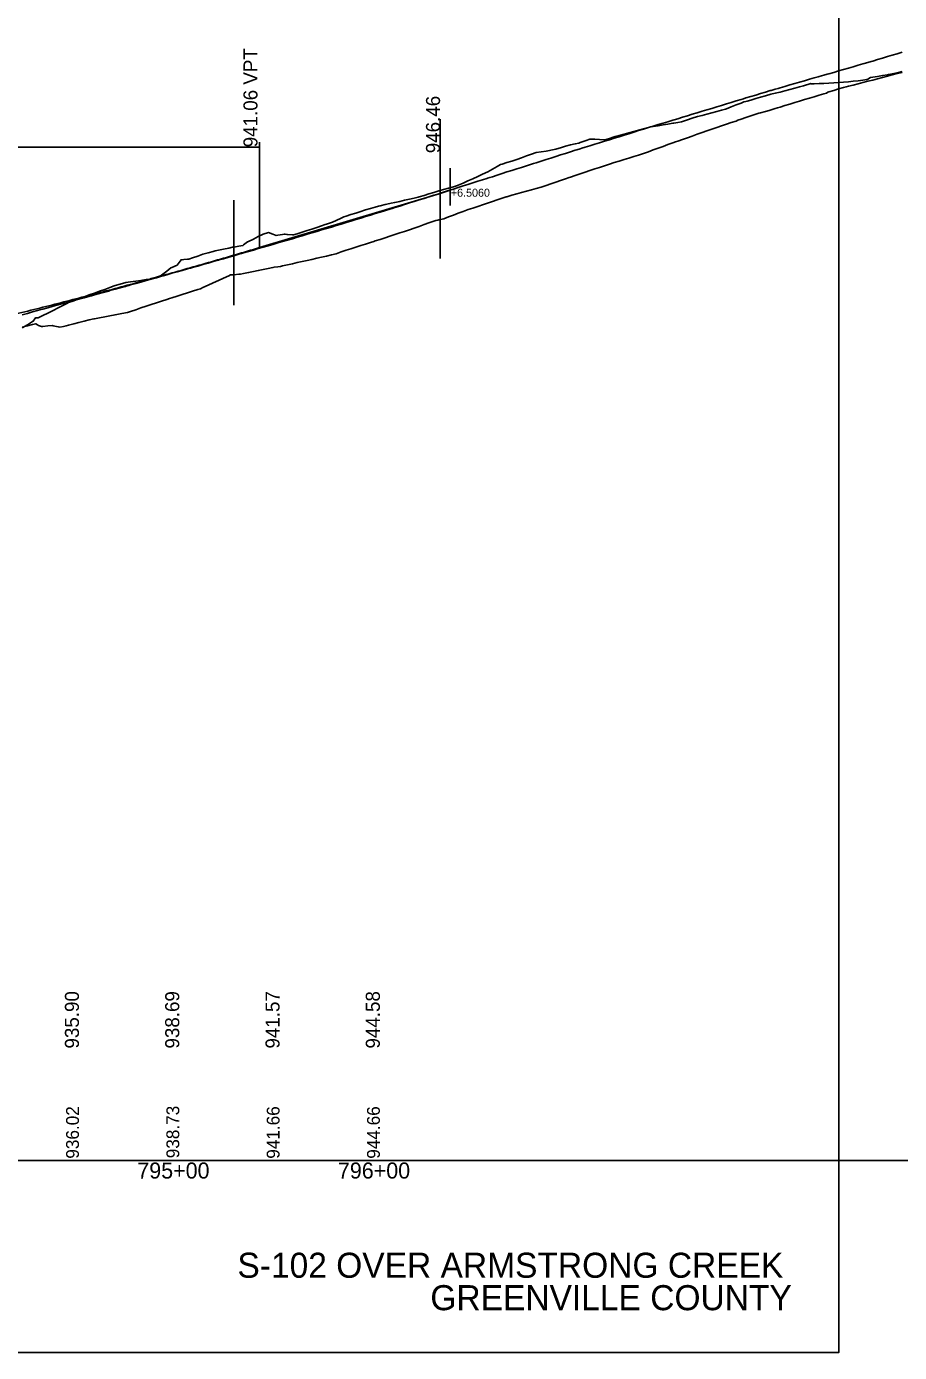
# Model space of a CAD drawing. Extents: x 1558113 to 1562835, y 1129435 to 1135883.
# Drawn here: x 1560920 to 1561355, y 1133348 to 1134009 of the extents above; entities that cross this region are included whole.
import ezdxf

# ---------------------------------------------------------------- set-up
doc = ezdxf.new("R2010")
doc.units = 0
for name, color, linetype in [('BR_EXIST_GROUND_LT', 7, 'Continuous'), ('BR_EXIST_GROUND_RT', 7, 'Continuous'), ('BR_USER NOTES', 7, 'Continuous'), ('RD_DDB_Profile_EX', 7, 'Continuous'), ('RD_DDB_Profile_Lbl', 7, 'Continuous'), ('RD_DDB_Profile_PR', 7, 'Continuous'), ('RD_DDB_StaTX', 7, 'Continuous'), ('RD_DDB_StripGrade', 7, 'Continuous'), ('RD_DDB_VCLbl', 7, 'Continuous'), ('RD_GPK_Profile_Cell', 7, 'Continuous'), ('RD_SHT_ShtClip', 7, 'Continuous'), ('RD_SHT_TX', 7, 'Continuous')]:
    doc.layers.add(name, color=color, linetype=linetype)

msp = doc.modelspace()

# ---------------------------------------------------------------- linework, layer by layer
at = {"layer": 'BR_EXIST_GROUND_LT'}
msp.add_lwpolyline([(1560918.07, 1133859.11), (1560920.65, 1133860.63), (1560923.22, 1133862.17), (1560923.59, 1133862.4), (1560924.66, 1133864.04), (1560925.98, 1133864.05), (1560928.37, 1133865.21), (1560930.94, 1133866.48), (1560933.52, 1133867.78), (1560936.09, 1133869.09), (1560938.66, 1133870.43), (1560940.26, 1133871.27), (1560941.24, 1133871.64), (1560943.81, 1133872.61), (1560946.39, 1133873.6), (1560947.43, 1133874), (1560948.96, 1133874.55), (1560950.25, 1133875.02), (1560951.53, 1133875.47), (1560954.11, 1133876.4), (1560956.68, 1133877.33), (1560959.26, 1133878.26), (1560961.83, 1133879.21), (1560963.97, 1133880), (1560964.4, 1133880.12), (1560966.98, 1133880.85), (1560969.81, 1133881.66), (1560972.13, 1133881.99), (1560974.7, 1133882.36), (1560977.27, 1133882.74), (1560979.85, 1133883.12), (1560981.76, 1133883.41), (1560982.42, 1133883.61), (1560985, 1133884.4), (1560987.09, 1133885.05), (1560987.57, 1133885.42), (1560990.14, 1133887.4), (1560992.17, 1133888.96), (1560992.72, 1133889.19), (1560995.29, 1133890.27), (1560997.29, 1133893.02), (1560997.87, 1133893.07), (1560998.72, 1133893.13), (1561000.44, 1133893.26), (1561001.12, 1133893.31), (1561003.02, 1133893.98), (1561005.59, 1133894.9), (1561008.2, 1133895.82), (1561009.4, 1133896.1), (1561010.74, 1133896.47), (1561013.31, 1133897.19), (1561014.24, 1133897.45), (1561015.89, 1133897.8), (1561018.46, 1133898.34), (1561021.03, 1133898.88), (1561022.88, 1133899.27), (1561023.61, 1133899.39), (1561026.04, 1133899.78), (1561028.1, 1133900.12), (1561028.47, 1133900.41), (1561030.38, 1133901.95), (1561030.9, 1133902.2), (1561033.33, 1133903.38), (1561035.76, 1133904.57), (1561038.23, 1133905.77), (1561040.82, 1133906.57), (1561043.06, 1133905.71), (1561044.68, 1133905.09), (1561045.49, 1133905.22), (1561047.92, 1133905.61), (1561048.66, 1133905.73), (1561049.18, 1133905.71), (1561049.98, 1133905.59), (1561050.35, 1133905.57), (1561052.78, 1133905.44), (1561053.27, 1133905.42), (1561055.21, 1133906.03), (1561057.64, 1133906.8), (1561060.07, 1133907.58), (1561062.5, 1133908.36), (1561064.93, 1133909.15), (1561067.36, 1133909.95), (1561069.13, 1133910.54), (1561069.8, 1133910.75), (1561072.23, 1133911.53), (1561072.81, 1133911.72), (1561074.66, 1133912.61), (1561077.09, 1133913.79), (1561078.44, 1133914.45), (1561079.52, 1133914.79), (1561081.95, 1133915.55), (1561084.38, 1133916.31), (1561086.81, 1133917.08), (1561088.74, 1133917.7), (1561089.24, 1133917.85), (1561091.67, 1133918.58), (1561094.11, 1133919.32), (1561095.69, 1133919.8), (1561096.54, 1133919.99), (1561098.97, 1133920.53), (1561101.4, 1133921.08), (1561102.03, 1133921.22), (1561103.83, 1133921.62), (1561106.26, 1133922.15), (1561108.69, 1133922.69), (1561111.12, 1133923.24), (1561113.55, 1133923.79), (1561115.41, 1133924.22), (1561115.98, 1133924.39), (1561118.42, 1133925.13), (1561120.85, 1133925.87), (1561123.28, 1133926.62), (1561125.74, 1133927.39), (1561128.14, 1133928.06), (1561130.57, 1133928.75), (1561133, 1133929.44), (1561135.05, 1133930.03), (1561135.43, 1133930.2), (1561137.86, 1133931.29), (1561140.29, 1133932.37), (1561142.73, 1133933.46), (1561145.16, 1133934.55), (1561147.59, 1133935.65), (1561150.25, 1133936.86), (1561152.45, 1133938.14), (1561154.88, 1133939.56), (1561156.52, 1133940.52), (1561157.31, 1133940.76), (1561159.74, 1133941.51), (1561162.17, 1133942.26), (1561162.58, 1133942.38), (1561164.6, 1133943.09), (1561167.03, 1133943.94), (1561169.47, 1133944.8), (1561171.9, 1133945.65), (1561174.28, 1133946.49), (1561176.76, 1133946.87), (1561179.19, 1133947.24), (1561180.9, 1133947.5), (1561181.62, 1133947.66), (1561184.05, 1133948.19), (1561184.59, 1133948.3), (1561186.48, 1133948.87), (1561188.91, 1133949.6), (1561191.46, 1133950.36), (1561193.78, 1133950.84), (1561195.56, 1133951.21), (1561196.21, 1133951.43), (1561198.64, 1133952.29), (1561199.7, 1133952.67), (1561200.52, 1133952.93), (1561201.07, 1133953.1), (1561201.44, 1133953.22), (1561203.5, 1133953.11), (1561205.93, 1133952.98), (1561208.48, 1133952.86), (1561210.79, 1133953.55), (1561213.22, 1133954.29), (1561213.75, 1133954.45), (1561215.65, 1133955), (1561218.09, 1133955.71), (1561218.74, 1133955.91), (1561220.54, 1133956.31), (1561222.95, 1133956.97), (1561225.38, 1133957.65), (1561227.81, 1133958.32), (1561230.25, 1133959.01), (1561231.24, 1133959.29), (1561232.67, 1133959.51), (1561235.1, 1133959.89), (1561237.53, 1133960.29), (1561239.96, 1133960.69), (1561242.4, 1133961.1), (1561242.83, 1133961.18), (1561244.83, 1133961.53), (1561246.79, 1133961.89), (1561247.26, 1133962.04), (1561249.69, 1133962.8), (1561252.12, 1133963.57), (1561254.76, 1133964.42), (1561256.98, 1133964.99), (1561259.41, 1133965.62), (1561261.84, 1133966.27), (1561264.27, 1133966.93), (1561266.7, 1133967.6), (1561268.6, 1133968.12), (1561269.14, 1133968.33), (1561271.57, 1133969.27), (1561274, 1133970.23), (1561276.43, 1133971.19), (1561277.8, 1133971.74), (1561278.86, 1133972.02), (1561279.43, 1133972.17), (1561281.29, 1133972.69), (1561283.72, 1133973.38), (1561286.15, 1133974.08), (1561288.58, 1133974.78), (1561291.21, 1133975.55), (1561293.45, 1133976.06), (1561295.88, 1133976.65), (1561298.31, 1133977.26), (1561300.74, 1133977.89), (1561303.17, 1133978.54), (1561305.6, 1133979.22), (1561307.52, 1133979.77), (1561308.03, 1133979.92), (1561310.68, 1133980.72), (1561311.06, 1133980.91), (1561311.43, 1133980.76), (1561312.89, 1133980.79), (1561315.32, 1133980.87), (1561317.76, 1133980.97), (1561320.19, 1133981.09), (1561322.62, 1133981.23), (1561325.05, 1133981.41), (1561327.48, 1133981.6), (1561329.91, 1133981.82), (1561332.34, 1133982.06), (1561334.77, 1133982.33), (1561337.2, 1133982.61), (1561339.15, 1133982.87), (1561339.63, 1133983.15), (1561340.94, 1133983.91), (1561342.06, 1133984.09), (1561344.5, 1133984.48), (1561346.93, 1133984.9), (1561349.36, 1133985.33), (1561349.91, 1133985.44), (1561351.79, 1133985.81), (1561354.22, 1133986.32), (1561356.65, 1133986.84)], dxfattribs=at)
at = {"layer": 'BR_EXIST_GROUND_RT'}
msp.add_lwpolyline([(1560918.07, 1133859.47), (1560920.65, 1133860.09), (1560923.22, 1133860.71), (1560924.86, 1133861.11), (1560925.79, 1133860.51), (1560926.14, 1133860.29), (1560927.65, 1133859.77), (1560928.37, 1133859.83), (1560930.94, 1133860.06), (1560933.09, 1133860.24), (1560933.52, 1133860.15), (1560936.09, 1133859.6), (1560936.79, 1133859.45), (1560938.66, 1133859.82), (1560939.93, 1133860.14), (1560941.24, 1133860.48), (1560943.81, 1133861.14), (1560946.39, 1133861.79), (1560948.96, 1133862.42), (1560951.53, 1133863.05), (1560953.75, 1133863.57), (1560954.11, 1133863.64), (1560956.68, 1133864.14), (1560959.26, 1133864.63), (1560961.83, 1133865.12), (1560964.4, 1133865.59), (1560966.98, 1133866.06), (1560969.55, 1133866.52), (1560970.59, 1133866.71), (1560972.13, 1133867.24), (1560974.7, 1133868.13), (1560977.27, 1133869.01), (1560979.85, 1133869.89), (1560982.42, 1133870.75), (1560985, 1133871.61), (1560987.57, 1133872.46), (1560990.14, 1133873.28), (1560991.59, 1133873.73), (1560992.72, 1133874.1), (1560995.29, 1133874.93), (1560997.87, 1133875.76), (1561000.44, 1133876.58), (1561003.02, 1133877.4), (1561005.59, 1133878.2), (1561006.9, 1133878.61), (1561008.16, 1133879.17), (1561010.74, 1133880.32), (1561013.31, 1133881.48), (1561015.89, 1133882.66), (1561018.46, 1133883.84), (1561021.03, 1133885.04), (1561021.9, 1133885.45), (1561023.61, 1133885.59), (1561026.04, 1133885.8), (1561026.87, 1133885.88), (1561028.47, 1133886.19), (1561030.9, 1133886.67), (1561033.33, 1133887.16), (1561035.76, 1133887.65), (1561038.19, 1133888.15), (1561040.62, 1133888.65), (1561043.06, 1133889.16), (1561043.75, 1133889.31), (1561045.49, 1133889.53), (1561046.8, 1133889.7), (1561047.92, 1133889.95), (1561050.35, 1133890.5), (1561052.78, 1133891.05), (1561055.21, 1133891.59), (1561057.64, 1133892.14), (1561060.07, 1133892.69), (1561062.5, 1133893.24), (1561064.93, 1133893.78), (1561067.36, 1133894.33), (1561069.8, 1133894.88), (1561072.23, 1133895.43), (1561074.66, 1133896.01), (1561077.09, 1133897.02), (1561079.52, 1133897.78), (1561081.95, 1133898.54), (1561084.38, 1133899.3), (1561086.81, 1133900.07), (1561089.24, 1133900.85), (1561091.67, 1133901.63), (1561093.44, 1133902.19), (1561094.11, 1133902.44), (1561096.54, 1133903.21), (1561098.97, 1133903.99), (1561101.4, 1133904.78), (1561103.83, 1133905.58), (1561106.26, 1133906.38), (1561108.69, 1133907.2), (1561111.12, 1133908.02), (1561113.55, 1133908.85), (1561115.98, 1133909.69), (1561118.42, 1133910.54), (1561120.85, 1133911.4), (1561123.28, 1133912.26), (1561124.2, 1133912.59), (1561125.26, 1133912.81), (1561125.71, 1133912.91), (1561128.3, 1133913.52), (1561130.57, 1133914.38), (1561133, 1133915.3), (1561135.43, 1133916.21), (1561137.86, 1133917.11), (1561140.45, 1133918.06), (1561142.73, 1133918.8), (1561145.16, 1133919.58), (1561145.78, 1133919.78), (1561147.59, 1133920.41), (1561150.02, 1133921.24), (1561152.45, 1133922.07), (1561154.88, 1133922.89), (1561157.31, 1133923.7), (1561159.38, 1133924.38), (1561159.74, 1133924.49), (1561162.17, 1133925.19), (1561164.6, 1133925.88), (1561167.03, 1133926.57), (1561169.47, 1133927.26), (1561171.9, 1133927.94), (1561174.33, 1133928.61), (1561176.76, 1133929.29), (1561179.19, 1133930.13), (1561181.62, 1133930.97), (1561184.05, 1133931.8), (1561186.48, 1133932.63), (1561188.91, 1133933.45), (1561190.72, 1133934.06), (1561191.34, 1133934.27), (1561193.78, 1133935.1), (1561196.21, 1133935.92), (1561196.67, 1133936.07), (1561198.64, 1133936.73), (1561201.07, 1133937.53), (1561203.5, 1133938.33), (1561205.93, 1133939.12), (1561208.36, 1133939.91), (1561210.79, 1133940.68), (1561213.22, 1133941.45), (1561215.65, 1133942.22), (1561218.09, 1133942.97), (1561220.52, 1133943.72), (1561222.95, 1133944.47), (1561225.38, 1133945.2), (1561226.84, 1133945.69), (1561227.34, 1133945.8), (1561227.81, 1133945.98), (1561230.24, 1133946.88), (1561232.67, 1133947.79), (1561235.1, 1133948.68), (1561237.53, 1133949.58), (1561239.96, 1133950.46), (1561242.4, 1133951.34), (1561243.8, 1133951.84), (1561244.83, 1133952.19), (1561247.26, 1133953.01), (1561249.69, 1133953.87), (1561252.12, 1133954.73), (1561254.55, 1133955.58), (1561256.98, 1133956.42), (1561259.41, 1133957.26), (1561261.84, 1133958.1), (1561264.27, 1133958.93), (1561266.7, 1133959.76), (1561269.14, 1133960.58), (1561271.57, 1133961.4), (1561274, 1133962.21), (1561274.76, 1133962.62), (1561276.43, 1133963.18), (1561278.86, 1133964), (1561281.29, 1133964.81), (1561283.72, 1133965.62), (1561285.3, 1133966.13), (1561286.15, 1133966.35), (1561288.58, 1133966.98), (1561289.33, 1133967.17), (1561291.01, 1133967.68), (1561293.45, 1133968.42), (1561294.64, 1133968.79), (1561295.88, 1133969.17), (1561298.31, 1133969.92), (1561300.74, 1133970.67), (1561303.17, 1133971.41), (1561305.6, 1133972.14), (1561308.03, 1133972.88), (1561310.46, 1133973.6), (1561312.89, 1133974.33), (1561315.32, 1133975.04), (1561317.76, 1133975.76), (1561319, 1133976.12), (1561319.74, 1133976.63), (1561320.19, 1133976.77), (1561322.62, 1133977.48), (1561325.05, 1133978.19), (1561327.48, 1133978.89), (1561328.83, 1133979.27), (1561329.91, 1133979.53), (1561332.34, 1133980.11), (1561334.77, 1133980.68), (1561337.2, 1133981.35), (1561339.63, 1133982.01), (1561342.06, 1133982.66), (1561344.5, 1133983.31), (1561346.93, 1133983.95), (1561349.36, 1133984.59), (1561351.79, 1133985.22), (1561354.22, 1133985.84), (1561356.65, 1133986.46)], dxfattribs=at)
at = {"layer": 'BR_USER NOTES'}
for p, q in [((1561126.37, 1133963.14), (1561126.37, 1133893.61)), ((1561131.37, 1133938.78), (1561131.37, 1133920.02)), ((1561126.37, 1133926.15), (1561131.37, 1133927.78)), ((1561023.61, 1133922.76), (1561023.61, 1133870.45))]:
    msp.add_line(p, q, dxfattribs=at)
at = {"layer": 'RD_DDB_Profile_EX'}
msp.add_lwpolyline([(1560918.07, 1133865.59), (1560920.65, 1133866.29), (1560923.22, 1133867), (1560925.79, 1133867.69), (1560926.92, 1133868), (1560928.37, 1133868.4), (1560930.94, 1133869.12), (1560933.52, 1133869.83), (1560936.09, 1133870.54), (1560938.66, 1133871.25), (1560941.24, 1133871.96), (1560943.81, 1133872.66), (1560946.39, 1133873.36), (1560948.96, 1133874.05), (1560951.81, 1133874.82), (1560952.56, 1133875.05), (1560954.11, 1133875.48), (1560956.68, 1133876.2), (1560959.26, 1133876.92), (1560961.2, 1133877.45), (1560961.83, 1133877.63), (1560964.4, 1133878.33), (1560966.98, 1133879.03), (1560969.55, 1133879.73), (1560970.4, 1133879.96), (1560971.31, 1133880.22), (1560972.13, 1133880.45), (1560974.7, 1133881.18), (1560977.27, 1133881.91), (1560979.85, 1133882.64), (1560982.42, 1133883.36), (1560985, 1133884.08), (1560987.57, 1133884.8), (1560988.43, 1133885.03), (1560990.14, 1133885.54), (1560990.72, 1133885.71), (1560992.72, 1133886.28), (1560995.29, 1133887), (1560997.87, 1133887.73), (1561000.44, 1133888.45), (1561001.93, 1133888.87), (1561003.02, 1133889.18), (1561005.59, 1133889.91), (1561008.16, 1133890.65), (1561010.74, 1133891.37), (1561013.31, 1133892.1), (1561015.89, 1133892.83), (1561016.2, 1133892.92), (1561018.46, 1133893.57), (1561021.03, 1133894.31), (1561023.61, 1133895.04), (1561026.04, 1133895.74), (1561027.33, 1133896.1), (1561028.47, 1133896.43), (1561030.22, 1133896.93), (1561030.9, 1133897.14), (1561033.33, 1133897.86), (1561035.76, 1133898.58), (1561038.19, 1133899.3), (1561040.62, 1133900.01), (1561043.06, 1133900.72), (1561045.49, 1133901.43), (1561047.92, 1133902.13), (1561050.35, 1133902.83), (1561052.78, 1133903.52), (1561055.21, 1133904.25), (1561057.64, 1133904.99), (1561060.07, 1133905.73), (1561062.5, 1133906.46), (1561064.93, 1133907.19), (1561067.36, 1133907.92), (1561069.8, 1133908.64), (1561072.23, 1133909.35), (1561074.66, 1133910.07), (1561077.09, 1133910.78), (1561079.52, 1133911.54), (1561081.95, 1133912.3), (1561084.38, 1133913.05), (1561086.81, 1133913.8), (1561089.24, 1133914.55), (1561091.67, 1133915.29), (1561094.11, 1133916.03), (1561096.54, 1133916.76), (1561099.17, 1133917.55), (1561101.4, 1133918.23), (1561102.98, 1133918.76), (1561103.83, 1133919.03), (1561106.26, 1133919.81), (1561108.69, 1133920.59), (1561111.12, 1133921.36), (1561113.55, 1133922.13), (1561115.98, 1133922.9), (1561118.42, 1133923.66), (1561120.85, 1133924.41), (1561123.28, 1133925.16), (1561125.36, 1133925.8), (1561125.71, 1133925.92), (1561127.14, 1133926.41), (1561128.14, 1133926.73), (1561130.57, 1133927.52), (1561133, 1133928.3), (1561135.43, 1133929.08), (1561137.86, 1133929.85), (1561140.29, 1133930.62), (1561142.73, 1133931.39), (1561145.16, 1133932.15), (1561147.59, 1133932.91), (1561149.63, 1133933.54), (1561150.02, 1133933.67), (1561151.13, 1133934.03), (1561152.45, 1133934.46), (1561154.88, 1133935.24), (1561157.31, 1133936.02), (1561159.74, 1133936.8), (1561162.17, 1133937.58), (1561164.6, 1133938.35), (1561167.03, 1133939.11), (1561169.47, 1133939.88), (1561171.99, 1133940.66), (1561172.99, 1133940.99), (1561174.33, 1133941.42), (1561176.76, 1133942.21), (1561179.19, 1133942.99), (1561181.62, 1133943.77), (1561184.05, 1133944.54), (1561186.48, 1133945.31), (1561188.91, 1133946.08), (1561191.34, 1133946.84), (1561193.78, 1133947.6), (1561194.54, 1133947.84), (1561196.21, 1133948.37), (1561197.02, 1133948.63), (1561198.64, 1133949.14), (1561201.07, 1133949.9), (1561203.5, 1133950.66), (1561205.93, 1133951.41), (1561208.36, 1133952.16), (1561210.79, 1133952.91), (1561213.22, 1133953.66), (1561215.65, 1133954.4), (1561217.67, 1133955.01), (1561218.09, 1133955.14), (1561218.66, 1133955.31), (1561220.52, 1133955.89), (1561222.95, 1133956.65), (1561225.38, 1133957.41), (1561227.81, 1133958.16), (1561230.24, 1133958.91), (1561232.67, 1133959.65), (1561235.1, 1133960.4), (1561237.53, 1133961.14), (1561239.96, 1133961.88), (1561240.89, 1133962.16), (1561242.4, 1133962.62), (1561243, 1133962.8), (1561244.83, 1133963.36), (1561247.26, 1133964.11), (1561249.69, 1133964.86), (1561252.12, 1133965.6), (1561254.55, 1133966.34), (1561256.98, 1133967.08), (1561259.41, 1133967.82), (1561261.87, 1133968.54), (1561264.27, 1133969.28), (1561266.7, 1133970.03), (1561269.14, 1133970.77), (1561271.57, 1133971.52), (1561274, 1133972.25), (1561276.43, 1133972.99), (1561277.59, 1133973.34), (1561278.86, 1133973.71), (1561281.29, 1133974.41), (1561283.72, 1133975.16), (1561286.15, 1133975.9), (1561288.58, 1133976.65), (1561291.01, 1133977.38), (1561291.39, 1133977.5), (1561293.45, 1133978.07), (1561294.87, 1133978.47), (1561295.88, 1133978.76), (1561298.31, 1133979.48), (1561300.74, 1133980.2), (1561303.17, 1133980.91), (1561305.6, 1133981.62), (1561308.03, 1133982.33), (1561310.46, 1133983.03), (1561312.89, 1133983.74), (1561314.87, 1133984.31), (1561315.32, 1133984.43), (1561317.76, 1133985.09), (1561319.32, 1133985.51), (1561320.19, 1133985.76), (1561322.62, 1133986.48), (1561325.05, 1133987.19), (1561327.48, 1133987.9), (1561329.91, 1133988.61), (1561332.34, 1133989.32), (1561334.77, 1133990.02), (1561337.2, 1133990.72), (1561337.76, 1133990.88), (1561339.63, 1133991.42), (1561341.25, 1133991.87), (1561342.06, 1133992.12), (1561344.5, 1133992.86), (1561346.93, 1133993.6), (1561349.36, 1133994.34), (1561351.79, 1133995.07), (1561354.22, 1133995.8), (1561356.65, 1133996.53)], dxfattribs=at)
at = {"layer": 'RD_DDB_Profile_PR'}
msp.add_line((1561036.37, 1133899.12), (1561126.37, 1133926.15), dxfattribs=at)
msp.add_spline([(1560436.37, 1133800.52), (1560448.37, 1133800.9), (1560460.37, 1133801.33), (1560472.37, 1133801.84), (1560484.37, 1133802.41), (1560496.37, 1133803.04), (1560508.37, 1133803.74), (1560520.37, 1133804.5), (1560532.37, 1133805.33), (1560544.37, 1133806.23), (1560556.37, 1133807.19), (1560568.37, 1133808.22), (1560580.37, 1133809.31), (1560592.37, 1133810.46), (1560604.37, 1133811.68), (1560616.37, 1133812.97), (1560628.37, 1133814.32), (1560640.37, 1133815.74), (1560652.37, 1133817.22), (1560664.37, 1133818.77), (1560676.37, 1133820.38), (1560688.37, 1133822.06), (1560700.37, 1133823.8), (1560712.37, 1133825.61), (1560724.37, 1133827.49), (1560736.37, 1133829.43), (1560748.37, 1133831.43), (1560760.37, 1133833.5), (1560772.37, 1133835.64), (1560784.37, 1133837.84), (1560796.37, 1133840.1), (1560808.37, 1133842.43), (1560820.37, 1133844.83), (1560832.37, 1133847.29), (1560844.37, 1133849.82), (1560856.37, 1133852.41), (1560868.37, 1133855.07), (1560880.37, 1133857.79), (1560892.37, 1133860.58), (1560904.37, 1133863.43), (1560916.37, 1133866.35), (1560928.37, 1133869.33), (1560940.37, 1133872.38), (1560952.37, 1133875.5), (1560964.37, 1133878.67), (1560976.37, 1133881.92), (1560988.37, 1133885.23), (1561000.37, 1133888.6), (1561012.37, 1133892.04), (1561024.37, 1133895.55), (1561036.37, 1133899.12)], degree=3, dxfattribs=at)
at = {"layer": 'RD_DDB_VCLbl'}
for p, q in [((1560436.37, 1133949.12), (1561036.37, 1133949.12)), ((1561036.37, 1133951.62), (1561036.37, 1133899.12))]:
    msp.add_line(p, q, dxfattribs=at)
at = {"layer": 'RD_GPK_Profile_Cell'}
msp.add_line((1558196.37, 1133443.84), (1562834.74, 1133443.84), dxfattribs=at)
at = {"layer": 'RD_SHT_ShtClip'}
msp.add_lwpolyline([(1559525.21, 1134448.11), (1561325.21, 1134448.11), (1561325.21, 1133348.11), (1559525.21, 1133348.11)], close=True, dxfattribs=at)

# ---------------------------------------------------------------- texts
at = {"layer": 'BR_USER NOTES'}
msp.add_text('+6.5060', height=4, dxfattribs=at).set_placement((1561131.76, 1133924.46))
at = {"layer": 'RD_DDB_Profile_Lbl'}
msp.add_text('946.46', height=7, rotation=90, dxfattribs=at).set_placement((1561126.37, 1133946.15))
at = {"layer": 'RD_DDB_StaTX'}
for s, p in [('795+00', (1560975.47, 1133434.84)), ('796+00', (1561075.47, 1133434.84))]:
    msp.add_text(s, height=8, dxfattribs=at).set_placement(p)
at = {"layer": 'RD_DDB_StripGrade'}
for s, height, p in [('941.06 VPT', 7, (1561035.37, 1133949.12)), ('935.90', 7, (1560946.37, 1133499.68)), ('938.69', 7, (1560996.37, 1133499.68)), ('941.57', 7, (1561046.37, 1133499.68)), ('944.58', 7, (1561096.37, 1133499.68)), ('936.02', 6.4, (1560946.37, 1133444.75)), ('938.73', 6.4, (1560996.37, 1133444.97)), ('941.66', 6.4, (1561046.37, 1133444.73)), ('944.66', 6.4, (1561096.37, 1133444.73))]:
    msp.add_text(s, height=height, rotation=90, dxfattribs=at).set_placement(p)
at = {"layer": 'RD_SHT_TX'}
for s, p in [('S-102 OVER ARMSTRONG CREEK', (1561025.37, 1133385.37)), ('GREENVILLE COUNTY', (1561121.53, 1133369.19))]:
    msp.add_text(s, height=12.4995, rotation=360, dxfattribs=at).set_placement(p)

doc.saveas('drawing.dxf')
